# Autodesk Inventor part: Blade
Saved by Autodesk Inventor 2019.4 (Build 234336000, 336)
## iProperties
Created: 2020-02
Part Number: Blade
Material: Generic
Document SubType Name: Modeling
Designer: Administrator
Density: 1 g/cm^3
Appearance: Default
Title: Blade v3
Author: Administrator
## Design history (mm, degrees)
feature "Body1"
body "Solid1"
